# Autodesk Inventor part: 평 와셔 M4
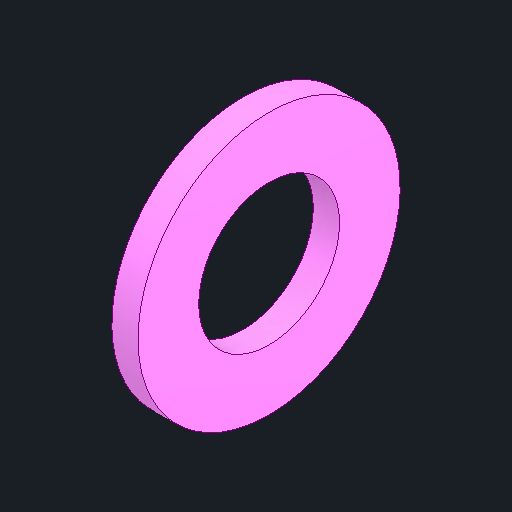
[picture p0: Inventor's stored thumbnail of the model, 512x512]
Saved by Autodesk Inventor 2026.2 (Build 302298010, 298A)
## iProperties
Created: 2026-03
Part Number: 평 와셔 M4
Material: 강철, 연강
Description: 평면 와셔
Document SubType Name: Modeling
Designer: PC2-02
Density: 7.85 g/cm^3
Appearance: 기본값
Author: jhkim
Sending System: Autodesk Inventor 2026
Preprocessor: ST-DEVELOPER v20.1
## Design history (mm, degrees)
feature "Solid1"
node "솔리드1"
